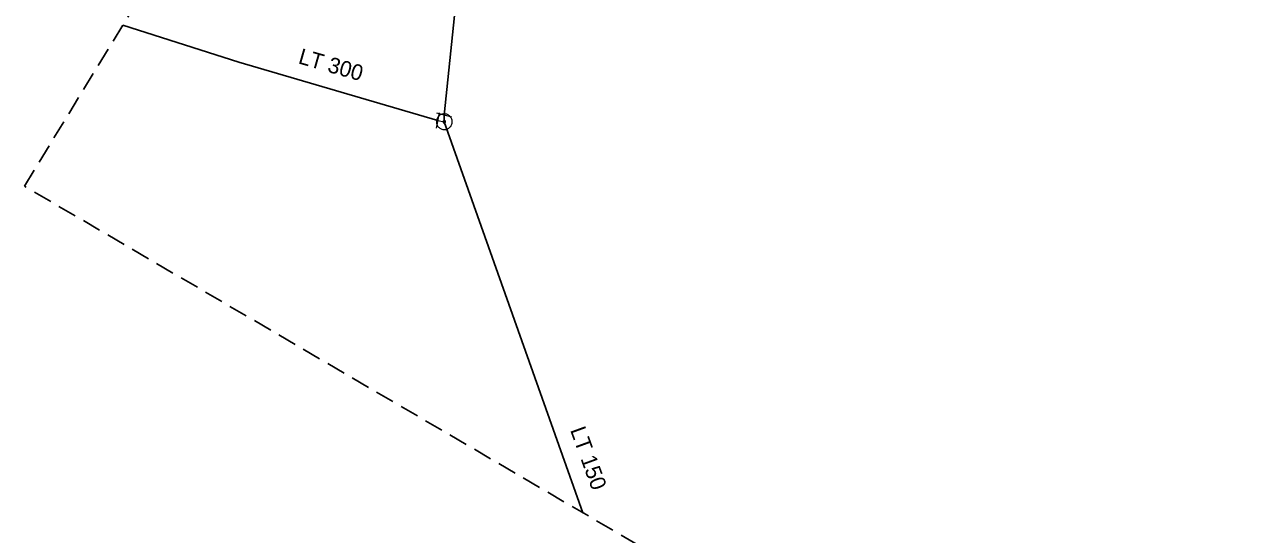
# Model space of a CAD drawing. Extents: x -774415 to -774100, y -975744 to -975502.
# Drawn here: x -774414.7 to -774337, y -975584 to -975551.5 of the extents above; entities that cross this region are included whole.
import ezdxf

# ---------------------------------------------------------------- set-up
doc = ezdxf.new("R2010")
doc.units = 0
doc.header["$LTSCALE"] = 0.4
doc.linetypes.add('MEDIUM_DASHED', pattern=[4.5, 3, -1.5])
for name, color, linetype, lineweight in [('1', 7, 'MEDIUM_DASHED', 25), ('14', 7, 'Continuous', 13), ('17', 7, 'Continuous', 25), ('34', 7, 'Continuous', 13), ('47', 7, 'Continuous', 13)]:
    doc.layers.add(name, color=color, linetype=linetype, lineweight=lineweight)

msp = doc.modelspace()

# ---------------------------------------------------------------- linework, layer by layer
at = {"layer": '1'}
msp.add_lwpolyline([(-774414.714, -975561.823), (-774378.138, -975501.935), (-774197.267, -975507.964), (-774100.401, -975732.645), (-774205.708, -975744.301), (-774260.773, -975651.856)], close=True, dxfattribs=at)
at = {"layer": '14'}
msp.add_line((-774388.44, -975557.649), (-774388.021, -975557.726), dxfattribs=at)
at = {"layer": '17'}
msp.add_line((-774388.021, -975557.726), (-774379.217, -975582.584), dxfattribs=at)
for points in [[(-774386.26, -975540.12), (-774388.021, -975557.302), (-774388.021, -975557.726)], [(-774408.464, -975551.589), (-774401.079, -975553.94), (-774388.44, -975557.649)]]:
    msp.add_lwpolyline(points, dxfattribs=at)
at = {"layer": '34'}
for p, q in [((-774388.346, -975557.157), (-774388.534, -975558.14)), ((-774387.537, -975557.429), (-774388.504, -975557.173))]:
    msp.add_line(p, q, dxfattribs=at)
at = {"layer": '47'}
for points in [[(-774387.532, -975557.617), (-774387.546, -975557.567), (-774387.566, -975557.518), (-774387.59, -975557.472), (-774387.618, -975557.429), (-774387.652, -975557.388), (-774387.69, -975557.351), (-774387.73, -975557.319), (-774387.775, -975557.291), (-774387.821, -975557.267), (-774387.87, -975557.249), (-774387.921, -975557.235), (-774387.973, -975557.228), (-774388.025, -975557.226), (-774388.077, -975557.229), (-774388.129, -975557.237), (-774388.179, -975557.251), (-774388.228, -975557.271), (-774388.275, -975557.295), (-774388.317, -975557.323), (-774388.358, -975557.357), (-774388.395, -975557.395), (-774388.428, -975557.436), (-774388.456, -975557.48), (-774388.479, -975557.526), (-774388.497, -975557.575), (-774388.511, -975557.626), (-774388.519, -975557.678), (-774388.52, -975557.73), (-774388.517, -975557.782), (-774388.509, -975557.834), (-774388.495, -975557.884), (-774388.475, -975557.933), (-774388.452, -975557.98), (-774388.423, -975558.022), (-774388.389, -975558.063), (-774388.352, -975558.1), (-774388.311, -975558.133), (-774388.267, -975558.161), (-774388.22, -975558.184), (-774388.171, -975558.202), (-774388.12, -975558.216), (-774388.069, -975558.224), (-774388.016, -975558.225), (-774387.964, -975558.222), (-774387.912, -975558.214), (-774387.862, -975558.2), (-774387.813, -975558.18), (-774387.767, -975558.157), (-774387.724, -975558.128), (-774387.683, -975558.094), (-774387.646, -975558.057), (-774387.614, -975558.016), (-774387.586, -975557.972), (-774387.562, -975557.925), (-774387.544, -975557.876), (-774387.53, -975557.825), (-774387.523, -975557.774), (-774387.521, -975557.721), (-774387.524, -975557.669)], [(-774387.94, -975557.708), (-774387.942, -975557.699), (-774387.946, -975557.692), (-774387.95, -975557.684), (-774387.954, -975557.677), (-774387.96, -975557.67), (-774387.966, -975557.664), (-774387.973, -975557.659), (-774387.98, -975557.654), (-774387.988, -975557.651), (-774387.996, -975557.647), (-774388.004, -975557.645), (-774388.013, -975557.644), (-774388.021, -975557.644), (-774388.029, -975557.643), (-774388.038, -975557.645), (-774388.047, -975557.647), (-774388.054, -975557.651), (-774388.062, -975557.655), (-774388.069, -975557.659), (-774388.076, -975557.665), (-774388.082, -975557.671), (-774388.087, -975557.678), (-774388.092, -975557.685), (-774388.096, -975557.693), (-774388.099, -975557.701), (-774388.101, -975557.709), (-774388.102, -975557.718), (-774388.102, -975557.726), (-774388.103, -975557.734), (-774388.101, -975557.743), (-774388.099, -975557.752), (-774388.095, -975557.759), (-774388.091, -975557.767), (-774388.087, -975557.774), (-774388.081, -975557.781), (-774388.076, -975557.787), (-774388.068, -975557.792), (-774388.061, -975557.797), (-774388.053, -975557.801), (-774388.045, -975557.804), (-774388.037, -975557.806), (-774388.028, -975557.807), (-774388.02, -975557.807), (-774388.012, -975557.808), (-774388.003, -975557.806), (-774387.994, -975557.804), (-774387.987, -975557.8), (-774387.979, -975557.796), (-774387.972, -975557.792), (-774387.965, -975557.786), (-774387.959, -975557.781), (-774387.954, -975557.773), (-774387.949, -975557.766), (-774387.946, -975557.758), (-774387.942, -975557.75), (-774387.94, -975557.742), (-774387.939, -975557.733), (-774387.939, -975557.725), (-774387.938, -975557.717)]]:
    msp.add_lwpolyline(points, close=True, dxfattribs=at)

# ---------------------------------------------------------------- texts
at = {"layer": '1'}
for s, rotation, p in [('LT 300', 344, (-774397.36, -975554.003)), ('LT 150', 290, (-774380.034, -975577.324))]:
    msp.add_text(s, height=1, rotation=rotation, dxfattribs=at).set_placement(p)

doc.saveas('drawing.dxf')
